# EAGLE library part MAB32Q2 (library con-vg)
CONNECTOR male, 32 pins, type Q/2, rows AB, grid 2.54 mm
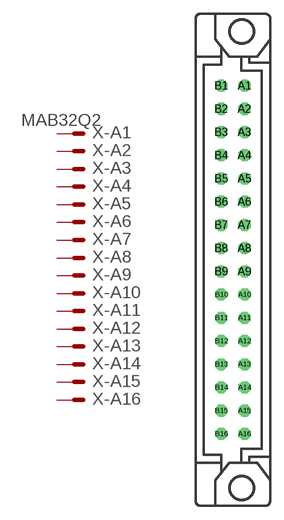
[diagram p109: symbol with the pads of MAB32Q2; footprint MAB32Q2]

Designator prefix X; gates -A1=MVAL -A2=MAL -A3=MAL -A4=MAL -A5=MAL -A6=MAL -A7=MAL -A8=MAL -A9=MAL -A10=MAL -A11=MAL -A12=MAL -A13=MAL -A14=MAL -A15=MAL -A16=MAL -B1=MVAL -B2=MAL -B3=MAL -B4=MAL -B5=MAL -B6=MAL -B7=MAL -B8=MAL -B9=MAL -B10=MAL -B11=MAL -B12=MAL -B13=MAL -B14=MAL -B15=MAL -B16=MAL

## MAB32Q2  [MAB32Q2]
A1  -A1:S  pas
A2  -A2:S  pas
A3  -A3:S  pas
A4  -A4:S  pas
A5  -A5:S  pas
A6  -A6:S  pas
A7  -A7:S  pas
A8  -A8:S  pas
A9  -A9:S  pas
A10  -A10:S  pas
A11  -A11:S  pas
A12  -A12:S  pas
A13  -A13:S  pas
A14  -A14:S  pas
A15  -A15:S  pas
A16  -A16:S  pas
B1  -B1:S  pas
B2  -B2:S  pas
B3  -B3:S  pas
B4  -B4:S  pas
B5  -B5:S  pas
B6  -B6:S  pas
B7  -B7:S  pas
B8  -B8:S  pas
B9  -B9:S  pas
B10  -B10:S  pas
B11  -B11:S  pas
B12  -B12:S  pas
B13  -B13:S  pas
B14  -B14:S  pas
B15  -B15:S  pas
B16  -B16:S  pas

## Footprint MAB32Q2 (pad centres in mm)
CONNECTOR male, 32 pins, type Q/2, rows AB, grid 2.54 mm
drill 0.813 octagon: A1 1.27,19.05; A2 1.27,16.51; A3 1.27,13.97; A4 1.27,11.43; A5 1.27,8.89; A6 1.27,6.35; A7 1.27,3.81; A8 1.27,1.27; A9 1.27,-1.27; A10 1.27,-3.81; A11 1.27,-6.35; A12 1.27,-8.89; A13 1.27,-11.43; A14 1.27,-13.97; A15 1.27,-16.51; A16 1.27,-19.05; B1 -1.27,19.05; B2 -1.27,16.51; B3 -1.27,13.97; B4 -1.27,11.43; B5 -1.27,8.89; B6 -1.27,6.35; B7 -1.27,3.81; B8 -1.27,1.27; B9 -1.27,-1.27; B10 -1.27,-3.81; B11 -1.27,-6.35; B12 -1.27,-8.89; B13 -1.27,-11.43; B14 -1.27,-13.97; B15 -1.27,-16.51; B16 -1.27,-19.05
hole 2.794 at 0.965,-25
hole 2.794 at 0.965,25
